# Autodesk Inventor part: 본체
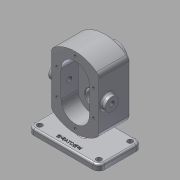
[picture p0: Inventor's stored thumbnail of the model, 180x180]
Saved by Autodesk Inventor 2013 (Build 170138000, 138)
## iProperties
Created: 2019-03
Part Number: 본체
Material: 알루미늄 6061
Document SubType Name: Modeling
Designer: Administrator
Density: 2.71 g/cm^3
Mass: 1191.56 g
Surface Area: 719.273 cm^2
Volume: 439.689 cm^3
Author: Administrator
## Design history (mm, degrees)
sketch "스케치1"
  geometry: L1 (-40, 60)-(40, 60); L2 (40, 60)-(40, -60); L3 (40, -60)-(-40, -60); L4 (-40, -60)-(-40, 60); L5 (-40, 60)-(40, -60); L6 (40, 60)-(-40, -60); A1 r 60 centre (0, 0) between (40, 44.721) and (-40, 44.721); A2 r 60 centre (0, 0) between (-40, -44.721) and (40, -44.721); 3 further points
  constraints: 12 end point, 6 point on circle, 4 midpoint, 4 point on line, 2 centre point, 2 parallel, 1 horizontal, 1 perpendicular
  dimensions: "d0" = 80 distance of L2.end L3.end; "d1" = 120 distance of L1.end L2.end; "d2" = 60 radius of A1; "d3" = 60 radius of A2
extrude "돌출1" new body sketch "스케치1" distance "d4" = 53; taper "d5" = 0 deg
sketch "스케치2"
  geometry: L1 (-24, -22)-(24, -22); L2 (24, -22)-(24, 22); L3 (24, 22)-(-24, 22); L4 (-24, 22)-(-24, -22); L5 (-24, -22)-(24, 22); L6 (24, -22)-(-24, 22); 3 further points
  constraints: 12 end point, 4 midpoint, 2 horizontal alignment, 2 parallel, 1 horizontal, 1 perpendicular, 4 other
  dimensions: "d6" = 48 distance of L3.end L2.end; "d7" = 44 distance of L2.end L1.end
extrude "돌출2" cut sketch "스케치2" distance "d8" = 29; taper "d9" = 0 deg
sketch "스케치3"
  geometry: C1 r 12.5 at (0, -22); C2 r 12.5 at (0, 22); A1 r 24 centre (0, 22) between (24, 22) and (-24, 22) reference; A2 r 24 centre (0, -22) between (-24, -22) and (24, -22) reference; 1 further point
  constraints: 2 centre point, 2 coincident
  dimensions: "d10" = 25 diameter of C1; "d11" = 25 diameter of C2
extrude "돌출3" cut sketch "스케치3" distance "d12" = 15; taper "d13" = 0 deg
sketch "스케치5"
  geometry: C1 r 19 at (0, 22); 1 further point
  constraints: 1 centre point
  dimensions: "d17" = 38 diameter of C1; "d18" = 22 distance of C1.centre point (0, 0)
extrude "돌출5" join sketch "스케치5" distance "d19" = 17; taper "d20" = 0 deg
sketch "스케치4"
  geometry: C1 r 12.5 at (0, 0) reference; C2 r 8.5 at (0, 0); 1 further point
  constraints: 1 centre point, 1 coincident
  dimensions: "d14" = 17 diameter of C2
extrude "돌출4" cut sketch "스케치4" stored distance "d15" = 15; taper "d16" = 0 deg
sketch "스케치8"
  geometry: L1 (3, -70)-(41, -70) reference; L2 (41, -53)-(3, -53) reference; L3 (13.5, -44)-(13.5, -70) reference; L4 (22, -53)-(22, -70); L5 (30.5, -44)-(30.5, -70) reference; L6 (22, -62.7)-(36, -62.7); L7 (36, -62.7)-(36, -69.3); L8 (36, -69.3)-(36.404, -70); 1 further point
  constraints: 8 end point, 2 midpoint, 2 perpendicular, 2 point on line
  dimensions: "d30" = 28 diameter of L7 L4; "d31" = 7.3 distance from line of L8.end L6; "d32" = 0.7 vertical distance of L8.end L7.end; "d33" = 30 deg angle of L8 L7
revolve "회전1" sketch "스케치8" stored, may be unused: angle "d34" = 90 deg
sketch "스케치9"
  geometry: L1 (0, 0)-(0, 89.443) reference; C1 r 11 at (14, 44.721); 2 further points
  constraints: 1 centre point, 1 horizontal alignment, 1 midpoint
  dimensions: "d35" = 22 diameter of C1; "d36" = 14 distance from line of C1.centre L1
extrude "돌출7" join sketch "스케치9" distance "d37" = 8; taper "d38" = 0 deg
sketch "스케치10"
  geometry: C1 r 11 at (0, 0) reference; 2 further points
  constraints: 1 coincident
hole "구멍1" sketch "스케치10" at (0, 0) diameter "d39" = 8.376; stored, may be unused: countersink angle "d43" = 90 deg, drill point angle "d45" = 118 deg; dims "d40" = 6, "d41" = 4, "d42" = 2, "d44" = 8
node "작업 평면1"
node "작업 평면2"
sketch "스케치13"
  geometry: L1 (-40, -53)-(40, -53) reference; L2 (60, -53)-(-60, -53); L3 (-60, -53)-(-60, 20); L4 (-60, 20)-(60, 20); L5 (60, 20)-(60, -53); 2 further points
  constraints: 8 end point, 2 midpoint, 2 parallel, 1 horizontal, 1 perpendicular
  dimensions: "d56" = 73 distance of L4.end L2.start; "d58" = 120 distance of L3.end L4.end
extrude "돌출9" join sketch "스케치13" distance "d59" = 10; taper "d60" = 0 deg
sketch "스케치14"
  geometry: L1 (60, 53)-(-60, 53) reference; L2 (-6, 53)-(6, 53); L3 (6, 53)-(6, 10); L4 (6, 10)-(-6, 10); L5 (-6, 10)-(-6, 53); 2 further points
  constraints: 8 end point, 2 parallel, 1 horizontal, 1 midpoint, 1 perpendicular, 1 point on line, 1 vertical alignment
  dimensions: "d61" = 43 distance of L4.end L2.start; "d63" = 12 distance of L3.end L4.end
extrude "돌출10" join sketch "스케치14" stored distance "d64" = 10; taper "d65" = 0 deg
fillet "모깎기1" dims "d66" = 10
fillet "모깎기2" dims "d67" = 10
fillet "모깎기4" dims "d69" = 3
fillet "모깎기5" dims "d70" = 3
fillet "모깎기6" dims "d71" = 3
fillet "모깎기7" dims "d72" = 3
sketch "스케치15"
  geometry: A1 r 7 centre (-50, 43) between (-50, 50) and (-57, 43) reference; A2 r 7 centre (-50, -10) between (-57, -10) and (-50, -17) reference; A3 r 7 centre (50, -10) between (50, -17) and (57, -10) reference; A4 r 7 centre (50, 43) between (57, 43) and (50, 50) reference; 5 further points
  constraints: 4 coincident
hole "구멍2" sketch "스케치15" at (-50, 43), (-50, -10), (50, -10), (50, 43) diameter "d73" = 9; stored, may be unused: countersink angle "d77" = 90 deg, drill point angle "d79" = 118 deg; dims "d74" = 6, "d75" = 4, "d76" = 2, "d78" = 8
fillet "모깎기8" dims "d80" = 0.5
chamfer "모따기1" distance "d81" = 1; stored, may be unused: second distance "d82" = 2, angle "d83" = 45 deg
fillet "모깎기9" dims "d84" = 3
fillet "모깎기10" dims "d85" = 3
sketch "스케치16"
  geometry: L1 (24, 22)-(24, -22) reference; L2 (0, 22)-(0, 53); L3 (0, 22)-(31, 22); L4 (0, 22)-(-31, 22); A1 r 24 centre (0, 22) between (24, 22) and (-24, 22) reference; 3 further points
  constraints: 6 end point, 3 coincident, 1 collinear, 1 parallel, 1 perpendicular
  dimensions: "d86" = 31 distance of L2.start L2.end; "d87" = 31 distance of L2.start L3.end; "d88" = 31 distance of L2.start L4.end
hole "구멍3" sketch "스케치16" at (0, 53), (31, 22), (-31, 22) diameter "d89" = 4.134; stored, may be unused: countersink angle "d93" = 90 deg, drill point angle "d95" = 118 deg; dims "d90" = 10, "d91" = 4, "d92" = 2, "d94" = 12
sketch "스케치17"
  geometry: L1 (-50, -20)-(50, -20) reference; L2 (-60, 43)-(-60, -10) reference; 2 further points
  constraints: 1 other
  dimensions: "d96" = 10 distance from line of L1 point (0, -10); "d97" = 60 distance from line of L2 point (0, -10)
feature "엠보싱1" sketch "스케치17" dims "d0" = 80, "d1" = 120, "d2" = 60, "d3" = 60, "d98" = 0.5, "d99" = 0
node "솔리드1"
mirror "대칭1"
mirror "대칭2"
other parameters: "d46" = -78, "d55" = -78
